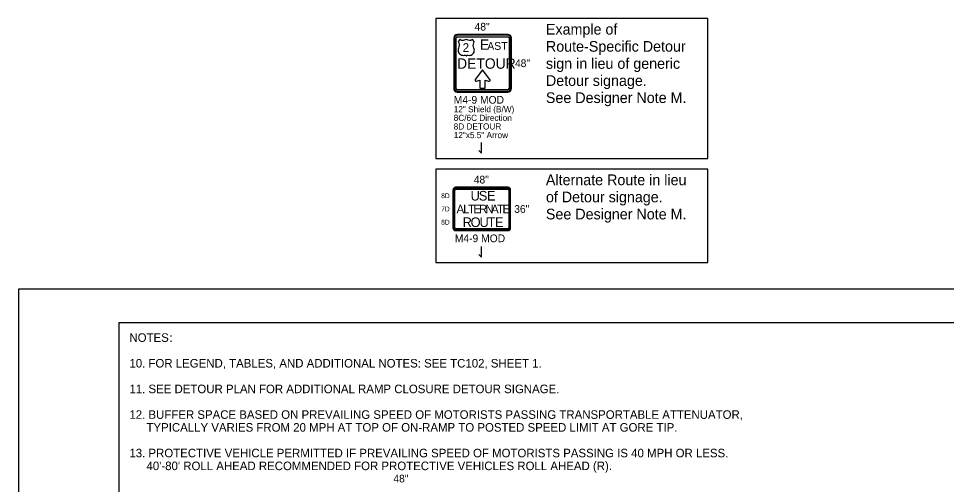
# Model space of a CAD drawing. Extents: x 99999.1 to 100055.7, y 99995 to 100013.2.
# Drawn here: x 100019.06 to 100027.75, y 100008.86 to 100013.22 of the extents above; entities that cross this region are included whole.
import ezdxf

# ---------------------------------------------------------------- set-up
doc = ezdxf.new("R2010")
doc.units = 0
for name, color, linetype in [('SH_GI_GeneralNotesBodyText', 7, 'Continuous'), ('SH_GI_PlotLimits', 7, 'Continuous'), ('SH_GI_SheetBorder', 7, 'Continuous'), ('TR_SN_ConstructionSigns', 7, 'Continuous'), ('TR_WZ_WorkZoneDetails', 7, 'Continuous')]:
    doc.layers.add(name, color=color, linetype=linetype)

msp = doc.modelspace()

# ---------------------------------------------------------------- linework, layer by layer
at = {"layer": 'SH_GI_PlotLimits'}
msp.add_lwpolyline([(100019.0625, 99999.6875), (100036.0625, 99999.6875), (100036.0625, 100010.6875), (100019.0625, 100010.6875)], close=True, dxfattribs=at)
at = {"layer": 'SH_GI_SheetBorder'}
for q in [(100020, 100000), (100035.75, 100010.375)]:
    msp.add_line((100020, 100010.375), q, dxfattribs=at)
at = {"layer": 'TR_SN_ConstructionSigns'}
for p, q in [((100023.1354, 100013.0373), (100023.1354, 100012.5648)), ((100023.1438, 100013.0373), (100023.1438, 100012.5648)), ((100023.1579, 100012.5648), (100023.1579, 100013.0373)), ((100023.6416, 100013.0711), (100023.1691, 100013.0711)), ((100023.6416, 100013.0626), (100023.1691, 100013.0626)), ((100023.1691, 100013.0486), (100023.6416, 100013.0486)), ((100023.6529, 100013.0373), (100023.6529, 100012.5648)), ((100023.6669, 100012.5648), (100023.6669, 100013.0373)), ((100023.6754, 100012.5648), (100023.6754, 100013.0373)), ((100023.6416, 100012.5536), (100023.1691, 100012.5536)), ((100023.1691, 100012.5395), (100023.6416, 100012.5395)), ((100023.1691, 100012.5311), (100023.6416, 100012.5311)), ((100023.6424, 100011.6405), (100023.153, 100011.6405)), ((100023.6424, 100011.6335), (100023.153, 100011.6335)), ((100023.153, 100011.6236), (100023.6424, 100011.6236)), ((100023.1277, 100011.6152), (100023.1277, 100011.2608)), ((100023.1347, 100011.6152), (100023.1347, 100011.2608)), ((100023.1446, 100011.2608), (100023.1446, 100011.6152)), ((100023.6508, 100011.6152), (100023.6508, 100011.2608)), ((100023.6607, 100011.2608), (100023.6607, 100011.6152)), ((100023.6677, 100011.2608), (100023.6677, 100011.6152)), ((100023.6424, 100011.2524), (100023.153, 100011.2524)), ((100023.153, 100011.2425), (100023.6424, 100011.2425)), ((100023.153, 100011.2355), (100023.6424, 100011.2355))]:
    msp.add_line(p, q, dxfattribs=at)
for points in [[(100023.2525, 100013.0237), (100023.2432, 100013.0187), (100023.2332, 100013.0156), (100023.2229, 100013.0143), (100023.2125, 100013.015), (100023.2024, 100013.0175), (100023.193, 100013.0218), (100023.177, 100013.0034), (100023.1824, 100012.9918), (100023.1855, 100012.9793), (100023.1862, 100012.9665), (100023.1845, 100012.9537), (100023.1802, 100012.9415), (100023.1772, 100012.9324), (100023.1761, 100012.9228), (100023.1769, 100012.9132), (100023.1797, 100012.904), (100023.1843, 100012.8954), (100023.1905, 100012.8881), (100023.1981, 100012.8821), (100023.2067, 100012.8778), (100023.2161, 100012.8754), (100023.2257, 100012.8749), (100023.2377, 100012.8766), (100023.2427, 100012.8762), (100023.2473, 100012.8743), (100023.2511, 100012.871), (100023.2525, 100012.869), (100023.2539, 100012.871), (100023.2577, 100012.8743), (100023.2623, 100012.8762), (100023.2673, 100012.8766), (100023.2794, 100012.8749), (100023.289, 100012.8754), (100023.2984, 100012.8778), (100023.3069, 100012.8821), (100023.3146, 100012.8881), (100023.3208, 100012.8954), (100023.3253, 100012.904), (100023.3281, 100012.9132), (100023.329, 100012.9228), (100023.3278, 100012.9324), (100023.3248, 100012.9415), (100023.3206, 100012.9537), (100023.3189, 100012.9665), (100023.3195, 100012.9793), (100023.3226, 100012.9918), (100023.328, 100013.0034), (100023.3121, 100013.0218), (100023.3027, 100013.0175), (100023.2925, 100013.015), (100023.2821, 100013.0143), (100023.2718, 100013.0156), (100023.2619, 100013.0187), (100023.2525, 100013.0237)], [(100023.3367, 100012.6494), (100023.3356, 100012.6478), (100023.335, 100012.6461), (100023.3347, 100012.6441), (100023.3348, 100012.6424), (100023.335, 100012.6412), (100023.3356, 100012.6398), (100023.3373, 100012.6375), (100023.3386, 100012.6364), (100023.34, 100012.6355), (100023.3417, 100012.6348), (100023.3432, 100012.6345), (100023.3447, 100012.6343), (100023.3465, 100012.6343), (100023.3478, 100012.6346), (100023.3795, 100012.6424), (100023.3795, 100012.5671), (100023.4307, 100012.5671), (100023.4307, 100012.6429), (100023.4617, 100012.6337), (100023.4647, 100012.6331), (100023.4681, 100012.6334), (100023.4703, 100012.6342), (100023.4733, 100012.6362), (100023.4752, 100012.6389), (100023.476, 100012.6414), (100023.4761, 100012.6436), (100023.4754, 100012.6463), (100023.4746, 100012.6477), (100023.4051, 100012.7405), (100023.3367, 100012.6494)]]:
    msp.add_lwpolyline(points, dxfattribs=at)
for centre, radius, start, end in [((100023.1691, 100013.0373), 0.0337, 90, 180), ((100023.1691, 100013.0373), 0.0253, 90, 180), ((100023.1691, 100013.0373), 0.0113, 90, 180), ((100023.6416, 100013.0373), 0.0338, 360, 90), ((100023.6416, 100013.0373), 0.0253, 360, 90), ((100023.6416, 100013.0373), 0.0113, 360, 90), ((100023.1691, 100012.5648), 0.0338, 180, 270), ((100023.1691, 100012.5648), 0.0253, 180, 270), ((100023.1691, 100012.5648), 0.0113, 180, 270), ((100023.6416, 100012.5648), 0.0337, 270, 360), ((100023.6416, 100012.5648), 0.0253, 270, 0), ((100023.6416, 100012.5648), 0.0113, 270, 0), ((100023.153, 100011.6152), 0.0253, 90, 180), ((100023.153, 100011.6152), 0.0183, 90, 180), ((100023.153, 100011.6152), 0.00844, 90, 180), ((100023.6424, 100011.6152), 0.0253, 360, 90), ((100023.6424, 100011.6152), 0.0183, 360, 90), ((100023.6424, 100011.6152), 0.00844, 360, 90), ((100023.153, 100011.2608), 0.0253, 180, 270), ((100023.153, 100011.2608), 0.0183, 180, 270), ((100023.153, 100011.2608), 0.00844, 180, 270), ((100023.6424, 100011.2608), 0.0253, 270, 360), ((100023.6424, 100011.2608), 0.0183, 270, 0), ((100023.6424, 100011.2608), 0.00844, 270, 0)]:
    msp.add_arc(centre, radius, start, end, dxfattribs=at)
at = {"layer": 'TR_WZ_WorkZoneDetails'}
for p, q in [((100023.3963, 100011.9605), (100023.3963, 100012.0605)), ((100023.3713, 100011.9855), (100023.3963, 100011.9605)), ((100023.3963, 100010.9875), (100023.3963, 100011.0875)), ((100023.3713, 100011.0125), (100023.3963, 100010.9875))]:
    msp.add_line(p, q, dxfattribs=at)
for points in [[(100022.9666, 100011.9105), (100025.5143, 100011.9105), (100025.5143, 100013.2191), (100022.9666, 100013.2191)], [(100022.9666, 100010.9375), (100025.5143, 100010.9375), (100025.5143, 100011.8105), (100022.9666, 100011.8105)]]:
    msp.add_lwpolyline(points, close=True, dxfattribs=at)

# ---------------------------------------------------------------- texts
at = {"layer": 'SH_GI_GeneralNotesBodyText'}
for s, p in [('NOTES', (100020.1, 100010.195)), (':', (100020.4743, 100010.195)), ('10. FOR LEGEND, TABLES, AND ADDITIONAL NOTES: SEE TC102, SHEET 1.', (100020.1, 100009.955)), ('11. SEE DETOUR PLAN FOR ADDITIONAL RAMP CLOSURE DETOUR SIGNAGE.', (100020.1, 100009.715)), ('12. BUFFER SPACE BASED ON PREVAILING SPEED OF MOTORISTS PASSING TRANSPORTABLE ATTENUATOR, ', (100020.1, 100009.475)), ('TYPICALLY VARIES FROM 20 MPH AT TOP OF ON-RAMP TO POSTED SPEED LIMIT AT GORE TIP.', (100020.26, 100009.355)), ('13. PROTECTIVE VEHICLE PERMITTED IF PREVAILING SPEED OF MOTORISTS PASSING IS 40 MPH OR LESS.  ', (100020.1, 100009.115)), ("40'-80' ROLL AHEAD RECOMMENDED FOR PROTECTIVE VEHICLES ROLL AHEAD (R).", (100020.26, 100008.995))]:
    msp.add_text(s, height=0.08, rotation=360, dxfattribs=at).set_placement(p)
at = {"layer": 'TR_SN_ConstructionSigns'}
for s, height, p in [('48"', 0.072, (100023.3306, 100013.1071)), ('E', 0.0972, (100023.3811, 100012.9267)), ('2', 0.081, (100023.2197, 100012.9076)), ('AST', 0.0729, (100023.4495, 100012.9267)), ('DETOUR', 0.0972, (100023.1668, 100012.7497)), ('48"', 0.072, (100023.7086, 100012.7651)), ('M4-9 MOD', 0.072, (100023.1354, 100012.4231)), ('8C/6C Direction', 0.0576, (100023.1354, 100012.2618)), ('12" Shield (B/W)', 0.0576, (100023.1354, 100012.3424)), ('8D DETOUR', 0.0576, (100023.1354, 100012.1811)), ('12"x5.5" Arrow', 0.0576, (100023.1354, 100012.1005)), ('48"', 0.072, (100023.323, 100011.6765)), ('36"', 0.072, (100023.7015, 100011.402)), ('M4-9 MOD', 0.072, (100023.1457, 100011.1275)), ('48"', 0.072, (100022.5705, 100008.8799))]:
    msp.add_text(s, height=height, rotation=360, dxfattribs=at).set_placement(p)
for s, height, p in [('8D', 0.045, (100023.018, 100011.5392)), ('U', 0.09, (100023.2933, 100011.5167)), ('S', 0.09, (100023.3698, 100011.5167)), ('E', 0.09, (100023.4463, 100011.5167)), ('7D', 0.045, (100023.018, 100011.4155)), ('A', 0.0787, (100023.1626, 100011.3986)), ('L', 0.0787, (100023.2241, 100011.3986)), ('T', 0.0787, (100023.269, 100011.3986)), ('E', 0.0787, (100023.3201, 100011.3986)), ('R', 0.0787, (100023.3737, 100011.3986)), ('N', 0.0787, (100023.4312, 100011.3986)), ('A', 0.0787, (100023.4863, 100011.3986)), ('T', 0.0787, (100023.5414, 100011.3986)), ('E', 0.0787, (100023.5926, 100011.3986)), ('8D', 0.045, (100023.018, 100011.2917)), ('R', 0.09, (100023.2186, 100011.2692)), ('O', 0.09, (100023.2933, 100011.2692)), ('U', 0.09, (100023.377, 100011.2692)), ('T', 0.09, (100023.4517, 100011.2692)), ('E', 0.09, (100023.521, 100011.2692))]:
    msp.add_text(s, height=height, dxfattribs=at).set_placement(p)
at = {"layer": 'TR_WZ_WorkZoneDetails'}
for s, p in [('Example of ', (100023.9983, 100013.0691)), ('Route-Specific Detour ', (100023.9983, 100012.9091)), ('sign in lieu of generic ', (100023.9983, 100012.7491)), ('Detour signage.', (100023.9983, 100012.5891)), ('See Designer Note M.', (100023.9983, 100012.4291)), ('Alternate Route in lieu ', (100023.9983, 100011.6605)), ('of Detour signage.', (100023.9983, 100011.5005)), ('See Designer Note M.', (100023.9983, 100011.3405))]:
    msp.add_text(s, height=0.1, dxfattribs=at).set_placement(p)

doc.saveas('drawing.dxf')
